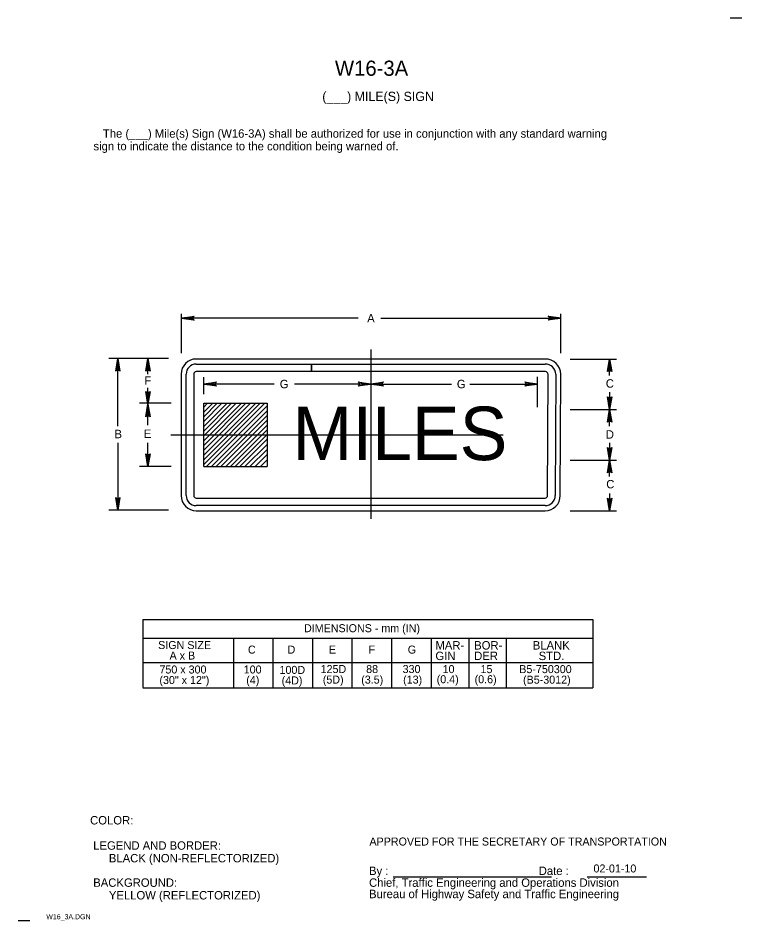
# Model space of a CAD drawing. Extents: x 0.004 to 0.219, y 0.004 to 0.272.
import ezdxf

# ---------------------------------------------------------------- set-up
doc = ezdxf.new("R2010")
doc.units = 0
for name, color, linetype in [('1', 7, 'Continuous'), ('11', 7, 'Continuous'), ('12', 7, 'Continuous'), ('2', 7, 'Continuous'), ('3', 7, 'Continuous'), ('4', 7, 'Continuous'), ('63', 7, 'Continuous')]:
    doc.layers.add(name, color=color, linetype=linetype)

# ---------------------------------------------------------------- blocks, each defined once
blk = doc.blocks.new('RARROW')
at = {"layer": '3'}
for p, q in [((-2.156, 0.285), (-2.2665, 0.384625)), ((-2.2665, 0.384625), (0, 0)), ((0, 0), (-2.2665, -0.379125)), ((-2.156, 0.285), (-2.075625, 0.12075)), ((0, 0), (-2.156, 0.285)), ((-2.14975, -0.2705), (0, 0)), ((-2.075625, 0.12075), (0, 0)), ((0, 0), (-2.074, -0.108)), ((-2.2665, -0.379125), (-2.14975, -0.2705)), ((-2.074, -0.108), (-2.14975, -0.2705))]:
    blk.add_line(p, q, dxfattribs=at)

msp = doc.modelspace()

# ---------------------------------------------------------------- linework, layer by layer
at = {"layer": '1'}
for p, q in [((0.11544, 0.01695), (0.16242, 0.01695)), ((0.17295, 0.01695), (0.19056, 0.01695))]:
    msp.add_line(p, q, dxfattribs=at)
at = {"layer": '11'}
for p, q in [((0.16049, 0.17059), (0.05699, 0.17059)), ((0.05249, 0.16609), (0.05249, 0.13009)), ((0.16499, 0.13009), (0.16512, 0.16609)), ((0.05699, 0.12559), (0.16049, 0.12559))]:
    msp.add_line(p, q, dxfattribs=at)
for centre, radius, start, end in [((0.05699, 0.16609), 0.0045, 90, 180), ((0.16056, 0.16603), 0.00456, 0.7848, 90.7848), ((0.05699, 0.13009), 0.0045, 180, 270), ((0.16049, 0.13009), 0.0045, 270, 0)]:
    msp.add_arc(centre, radius, start, end, dxfattribs=at)
at = {"layer": '12'}
for p, q in [((0.05924, 0.14209), (0.07462, 0.15746)), ((0.05924, 0.14071), (0.07599, 0.15746)), ((0.05924, 0.14496), (0.07174, 0.15746)), ((0.05924, 0.14359), (0.07312, 0.15746)), ((0.05924, 0.14634), (0.07037, 0.15746)), ((0.05924, 0.14784), (0.06887, 0.15746)), ((0.05924, 0.14921), (0.06749, 0.15746)), ((0.05924, 0.15059), (0.06612, 0.15746)), ((0.05924, 0.15209), (0.06462, 0.15746)), ((0.05924, 0.15346), (0.06324, 0.15746)), ((0.05924, 0.15484), (0.06187, 0.15746)), ((0.05924, 0.13934), (0.07737, 0.15746)), ((0.05924, 0.15746), (0.07799, 0.15746)), ((0.05924, 0.15633), (0.06037, 0.15746)), ((0.05999, 0.13871), (0.07799, 0.15671)), ((0.06149, 0.13871), (0.07799, 0.15521)), ((0.06287, 0.13871), (0.07799, 0.15384)), ((0.06424, 0.13871), (0.07799, 0.15246)), ((0.06574, 0.13871), (0.07799, 0.15096)), ((0.06712, 0.13871), (0.07799, 0.14959)), ((0.06849, 0.13871), (0.07799, 0.14821)), ((0.0699, 0.13871), (0.07799, 0.14681)), ((0.07144, 0.13871), (0.07799, 0.14526)), ((0.07292, 0.13871), (0.07799, 0.14379)), ((0.07446, 0.13871), (0.07799, 0.14225)), ((0.07607, 0.13871), (0.07799, 0.14064)), ((0.05924, 0.13871), (0.07799, 0.13871))]:
    msp.add_line(p, q, dxfattribs=at)
for points in [[(0.05924, 0.13871), (0.05924, 0.15746)], [(0.07799, 0.15746), (0.07799, 0.13871)]]:
    msp.add_lwpolyline(points, dxfattribs=at)
at = {"layer": '3'}
for p, q in [((0.05262, 0.17234), (0.05262, 0.18396)), ((0.10501, 0.18271), (0.05262, 0.18271)), ((0.11172, 0.18271), (0.16512, 0.18271)), ((0.16512, 0.17234), (0.16512, 0.18396)), ((0.10874, 0.17346), (0.10874, 0.12321)), ((0.04873, 0.17071), (0.03104, 0.17071)), ((0.03373, 0.15071), (0.03373, 0.17071)), ((0.04265, 0.16612), (0.04265, 0.17071)), ((0.05699, 0.16909), (0.09122, 0.16909)), ((0.09122, 0.16909), (0.09122, 0.16684)), ((0.09122, 0.16684), (0.09122, 0.16909)), ((0.09122, 0.16909), (0.16051, 0.16909)), ((0.16787, 0.17059), (0.18162, 0.17059)), ((0.17962, 0.16571), (0.17962, 0.17059)), ((0.05399, 0.13009), (0.05399, 0.16609)), ((0.05624, 0.16609), (0.05624, 0.13009)), ((0.09122, 0.16684), (0.05699, 0.16684)), ((0.16055, 0.16684), (0.09122, 0.16684)), ((0.05924, 0.16019), (0.05924, 0.16521)), ((0.15824, 0.15631), (0.15824, 0.16531)), ((0.16124, 0.13009), (0.16137, 0.16604)), ((0.16362, 0.16607), (0.16349, 0.13009)), ((0.04265, 0.1572), (0.04265, 0.16203)), ((0.08009, 0.16316), (0.05924, 0.16316)), ((0.10874, 0.16316), (0.08612, 0.16316)), ((0.10874, 0.16316), (0.13276, 0.16316)), ((0.13812, 0.16316), (0.15824, 0.16316)), ((0.17962, 0.16071), (0.17962, 0.15559)), ((0.04953, 0.15746), (0.04015, 0.15746)), ((0.04265, 0.15098), (0.04265, 0.1572)), ((0.16787, 0.15559), (0.18162, 0.15559)), ((0.17962, 0.15071), (0.17962, 0.15559)), ((0.0494, 0.14809), (0.14803, 0.14809)), ((0.03373, 0.14571), (0.03373, 0.12571)), ((0.04265, 0.13871), (0.04265, 0.14575)), ((0.17962, 0.14571), (0.17962, 0.14059)), ((0.16787, 0.14059), (0.18162, 0.14059)), ((0.17962, 0.13571), (0.17962, 0.14059)), ((0.04953, 0.13871), (0.04015, 0.13871)), ((0.05699, 0.12934), (0.16049, 0.12934)), ((0.17962, 0.13071), (0.17962, 0.12559)), ((0.16049, 0.12709), (0.05699, 0.12709)), ((0.04873, 0.12571), (0.03104, 0.12571)), ((0.16787, 0.12559), (0.18162, 0.12559)), ((0.04119, 0.09335), (0.04119, 0.0731)), ((0.04119, 0.09329), (0.17461, 0.09329)), ((0.17461, 0.09333), (0.17461, 0.07308)), ((0.17461, 0.08767), (0.04119, 0.08767)), ((0.06802, 0.0877), (0.06802, 0.0731)), ((0.07969, 0.08772), (0.07969, 0.0731)), ((0.09144, 0.08772), (0.09144, 0.0731)), ((0.10319, 0.08772), (0.10319, 0.0731)), ((0.11494, 0.08772), (0.11494, 0.0731)), ((0.12669, 0.08768), (0.12669, 0.07308)), ((0.13781, 0.08768), (0.13781, 0.07308)), ((0.14894, 0.08768), (0.14894, 0.07308)), ((0.04119, 0.08054), (0.17461, 0.08054)), ((0.04119, 0.07304), (0.17461, 0.07304))]:
    msp.add_line(p, q, dxfattribs=at)
for centre, radius, start, end in [((0.05699, 0.16609), 0.003, 90, 180), ((0.16056, 0.16603), 0.00306, 0.7848, 90.7848), ((0.05699, 0.16609), 0.00075, 90, 180), ((0.16056, 0.16603), 0.000813, 0.7848, 90.7848), ((0.05699, 0.13009), 0.003, 180, 270), ((0.05699, 0.13009), 0.00075, 180, 270), ((0.16049, 0.13009), 0.00075, 270, 0), ((0.16049, 0.13009), 0.003, 270, 0)]:
    msp.add_arc(centre, radius, start, end, dxfattribs=at)
at = {"layer": '63'}
for p, q in [((0.21888, 0.27175), (0.21538, 0.27175)), ((0.00762, 0.00387), (0.00413, 0.00387))]:
    msp.add_line(p, q, dxfattribs=at)

# ---------------------------------------------------------------- block references
at = {"layer": '3', "xscale": 0.0016545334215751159, "yscale": 0.0016366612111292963}
for p, rotation in [((0.05262, 0.18271), 180), ((0.03373, 0.17071), 90), ((0.04265, 0.17071), 90), ((0.17962, 0.17059), 90), ((0.05924, 0.16316), 180), ((0.10874, 0.16316), 180), ((0.04265, 0.1572), -90), ((0.17962, 0.15559), -90), ((0.04265, 0.1572), 90), ((0.17962, 0.15559), 90), ((0.04265, 0.13871), -90), ((0.17962, 0.14059), -90), ((0.17962, 0.14059), 90), ((0.03373, 0.12571), -90), ((0.17962, 0.12559), -90)]:
    msp.add_blockref('RARROW', p, dxfattribs=dict(at, rotation=rotation))
for p in [(0.16512, 0.18271), (0.10874, 0.16316), (0.15824, 0.16316)]:
    msp.add_blockref('RARROW', p, dxfattribs=at)

# ---------------------------------------------------------------- texts
at = {"layer": '1'}
for s, height, p in [('W16-3A', 0.0045, (0.09813, 0.25462)), ('(___) MILE(S) SIGN', 0.0027503, (0.09438, 0.24713)), ('COLOR:', 0.0025, (0.0255, 0.0325)), (' LEGEND AND BORDER:', 0.0024998, (0.0255, 0.025)), ('APPROVED FOR THE SECRETARY OF TRANSPORTATION', 0.0023752, (0.10837, 0.02625)), ('      BLACK (NON-REFLECTORIZED)', 0.0024998, (0.0255, 0.02125)), ('By :                                                Date :', 0.0024998, (0.10825, 0.0175)), (' BACKGROUND:', 0.0024998, (0.0255, 0.014)), ('Chief, Traffic Engineering and Operations Division', 0.0024998, (0.10825, 0.014)), ('      YELLOW (REFLECTORIZED)', 0.0024998, (0.0255, 0.01025)), ('Bureau of Highway Safety and Traffic Engineering', 0.0024998, (0.10825, 0.01063)), ('W16_3A.DGN', 0.0015, (0.0125, 0.00438))]:
    msp.add_text(s, height=height, dxfattribs=at).set_placement(p)
at = {"layer": '12'}
msp.add_text('MILES', height=0.015875, dxfattribs=at).set_placement((0.08558, 0.14059))
at = {"layer": '2'}
for s, height, p in [('   The (___) Mile(s) Sign (W16-3A) shall be authorized for use in conjunction with any standard warning', 0.00249975, (0.0265, 0.23625)), ('sign to indicate the distance to the condition being warned of.', 0.0024998, (0.0265, 0.2325))]:
    msp.add_text(s, height=height, dxfattribs=at).set_placement(p)
at = {"layer": '3'}
for s, height, p in [('A', 0.0025, (0.1077, 0.18146)), ('F', 0.0025, (0.0416, 0.16294)), ('G', 0.0025, (0.08177, 0.16191)), ('G', 0.0025, (0.1343, 0.16191)), ('C', 0.0025, (0.17849, 0.16209)), ('B', 0.0025, (0.03273, 0.14709)), ('E', 0.0025, (0.04144, 0.14717)), ('D', 0.0025, (0.17849, 0.14696)), ('C', 0.0025, (0.17862, 0.13221)), ('DIMENSIONS - mm (IN)', 0.0023752, (0.08896, 0.08954)), ('SIGN SIZE', 0.002375, (0.04569, 0.08454)), ('MAR-', 0.0025, (0.12794, 0.0844)), ('BOR-', 0.0025, (0.13944, 0.0844)), ('BLANK', 0.0025, (0.15682, 0.0844)), ('A x B', 0.002375, (0.04907, 0.08142)), ('C', 0.00238, (0.07232, 0.08319)), ('D', 0.00238, (0.08407, 0.08319)), ('E', 0.00238, (0.09632, 0.08319)), ('F', 0.00238, (0.1081, 0.08319)), ('G', 0.00238, (0.11974, 0.08319)), ('GIN', 0.0025, (0.12794, 0.08127)), ('DER', 0.0025, (0.13944, 0.08127)), ('STD.', 0.0025, (0.15857, 0.08127)), ('750 x 300', 0.002375, (0.04607, 0.07729)), ('100', 0.002375, (0.07107, 0.07729)), ('100D', 0.002375, (0.08169, 0.07717)), ('125D', 0.002375, (0.09388, 0.07742)), ('88', 0.002375, (0.10739, 0.07742)), ('330', 0.002375, (0.11821, 0.07742)), ('10', 0.002375, (0.13007, 0.0774)), ('15', 0.002375, (0.14132, 0.0774)), ('B5-750300', 0.002375, (0.15282, 0.0774)), ('(30" x 12")', 0.0023752, (0.04607, 0.07417)), ('(4)', 0.002375, (0.07182, 0.07417)), ('(4D)', 0.002375, (0.08232, 0.07404)), ('(5D)', 0.002375, (0.09453, 0.07429)), ('(3.5)', 0.002375, (0.10593, 0.07429)), ('(13)', 0.002375, (0.11836, 0.07429)), ('(0.4)', 0.002375, (0.12832, 0.0744)), ('(0.6)', 0.002375, (0.13957, 0.0744)), ('(B5-3012)', 0.002375, (0.15394, 0.07427))]:
    msp.add_text(s, height=height, dxfattribs=at).set_placement(p)
at = {"layer": '4'}
msp.add_text('02-01-10', height=0.002375, dxfattribs=at).set_placement((0.17483, 0.01826))

doc.saveas('drawing.dxf')
